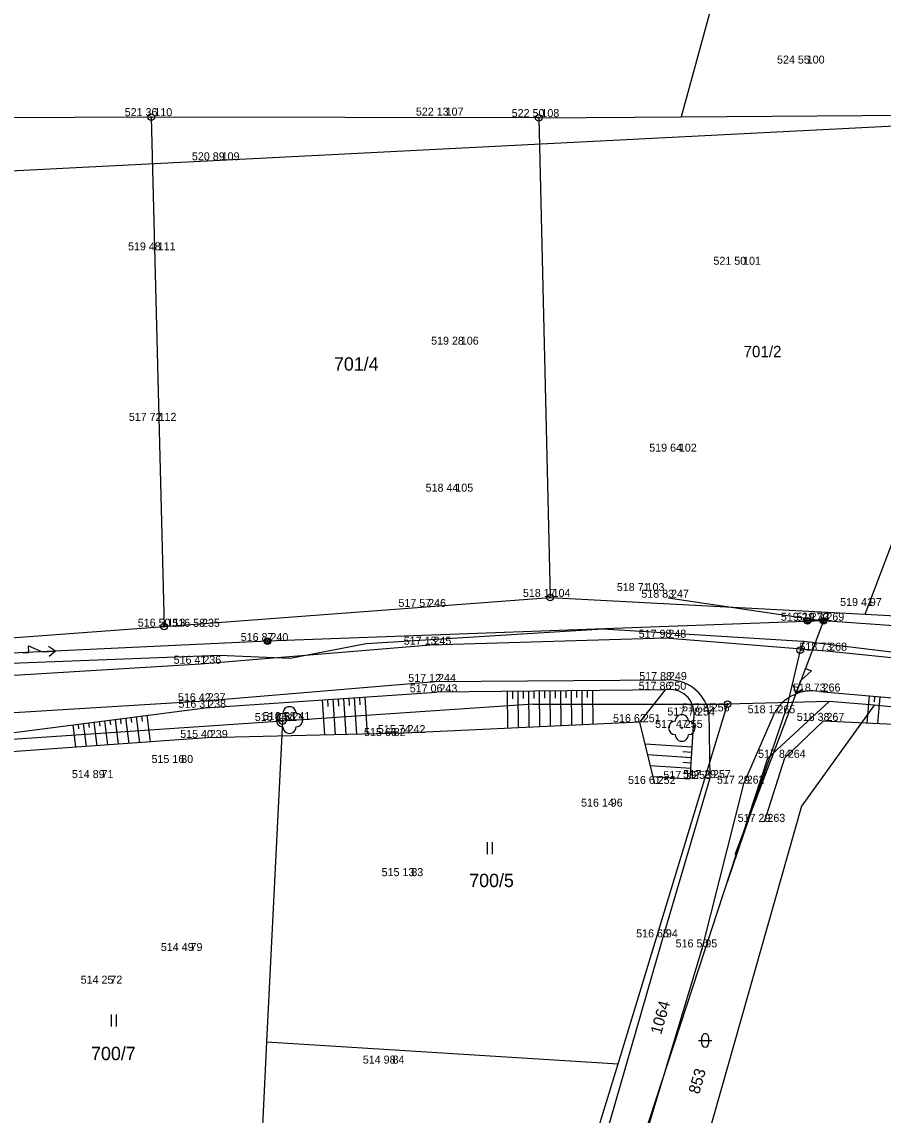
# Model space of a CAD drawing. Extents: x -553108 to -552267, y -1076883 to -1076631.
# Drawn here: x -552892.1 to -552827.6, y -1076828.5 to -1076746.6 of the extents above; entities that cross this region are included whole.
import ezdxf

# ---------------------------------------------------------------- set-up
doc = ezdxf.new("R2010")
doc.units = 0
for name, color, linetype in [('Vrstva 1', 7, 'Continuous'), ('Vrstva 12', 7, 'Continuous'), ('Vrstva 16', 7, 'Continuous'), ('Vrstva 17', 7, 'Continuous'), ('Vrstva 2', 7, 'Continuous'), ('Vrstva 20', 7, 'Continuous'), ('Vrstva 21', 7, 'Continuous'), ('Vrstva 26', 7, 'Continuous'), ('Vrstva 27', 7, 'Continuous'), ('Vrstva 3', 7, 'Continuous'), ('Vrstva 33', 7, 'Continuous'), ('Vrstva 4', 7, 'Continuous'), ('Vrstva 46', 7, 'Continuous'), ('Vrstva 5', 7, 'Continuous'), ('Vrstva 53', 7, 'Continuous'), ('Vrstva 6', 7, 'Continuous')]:
    doc.layers.add(name, color=color, linetype=linetype)

msp = doc.modelspace()

# ---------------------------------------------------------------- linework, layer by layer
at = {"layer": 'Vrstva 1'}
for centre in [(-552872.06, -1076798.89), (-552842.65, -1076799.48)]:
    msp.add_circle(centre, 0.05, dxfattribs=at)
for centre, start, end in [((-552872.559, -1076798.89), 90.11832, 269.88168), ((-552872.06, -1076798.386), 359.57041, 180.42959), ((-552871.563, -1076798.89), 270.29937, 89.70063), ((-552843.149, -1076799.48), 90.11832, 269.88168), ((-552842.65, -1076798.976), 359.57041, 180.42959), ((-552842.153, -1076799.48), 270.29937, 89.70063), ((-552872.06, -1076799.391), 179.84171, 0.15829), ((-552842.65, -1076799.981), 179.84171, 0.15829)]:
    msp.add_arc(centre, 0.5, start, end, dxfattribs=at)
at = {"layer": 'Vrstva 12'}
for p, q in [((-552834.93, -1076801.72), (-552832.03, -1076798.95)), ((-552832.03, -1076798.95), (-552822.54, -1076799.41)), ((-552836.46, -1076806.52), (-552834.93, -1076801.72))]:
    msp.add_line(p, q, dxfattribs=at)
at = {"layer": 'Vrstva 16'}
for p, q in [((-552891.597, -1076793.813), (-552891.62, -1076793.313)), ((-552891.62, -1076793.313), (-552890.598, -1076793.766)), ((-552889.599, -1076793.719), (-552890.116, -1076793.368)), ((-552892.096, -1076793.836), (-552891.597, -1076793.813)), ((-552890.598, -1076793.766), (-552889.599, -1076793.719)), ((-552889.599, -1076793.719), (-552890.081, -1076794.117)), ((-552833.214, -1076794.548), (-552833.391, -1076795.015)), ((-552833.391, -1076795.015), (-552832.923, -1076795.192)), ((-552832.923, -1076795.192), (-552833.745, -1076795.95)), ((-552834.1, -1076796.885), (-552834.273, -1076796.285)), ((-552833.745, -1076795.95), (-552834.1, -1076796.885)), ((-552834.1, -1076796.885), (-552833.572, -1076796.551))]:
    msp.add_line(p, q, dxfattribs=at)
at = {"layer": 'Vrstva 17'}
for p, q in [((-552878.74, -1076794.67), (-552861.49, -1076793.24)), ((-552861.49, -1076793.24), (-552843.88, -1076792.72)), ((-552843.88, -1076792.72), (-552831.83, -1076793.69)), ((-552831.83, -1076793.69), (-552822.33, -1076794.68)), ((-552894.1, -1076795.62), (-552878.74, -1076794.67)), ((-552843.84, -1076795.89), (-552861.15, -1076796.03)), ((-552861.15, -1076796.03), (-552878.42, -1076797.48)), ((-552832.32, -1076796.75), (-552822.3, -1076797.63)), ((-552878.42, -1076797.48), (-552893.95, -1076798.43)), ((-552840.63, -1076798.24), (-552840.54, -1076803.24)), ((-552838.01, -1076803.66), (-552835.71, -1076798.38)), ((-552840.54, -1076803.24), (-552844.07, -1076815.18)), ((-552841.11, -1076815.93), (-552838.01, -1076803.66)), ((-552844.07, -1076815.18), (-552848.68, -1076831.13)), ((-552845.93, -1076831.93), (-552841.11, -1076815.93))]:
    msp.add_line(p, q, dxfattribs=at)
for centre, radius, start, end in [((-552843.623, -1076798.961), 3.079, 13.54648, 94.03876), ((-552832.896, -1076799.892), 3.194, 79.6051, 151.75381)]:
    msp.add_arc(centre, radius, start, end, dxfattribs=at)
at = {"layer": 'Vrstva 2'}
for p, q in [((-552848.57, -1076792.08), (-552866.31, -1076793.17)), ((-552833.59, -1076793), (-552848.57, -1076792.08)), ((-552866.31, -1076793.17), (-552872.01, -1076794.27)), ((-552833.509, -1076793.01), (-552833.778, -1076793.66)), ((-552833.509, -1076793.01), (-552833.59, -1076793)), ((-552822.72, -1076794.32), (-552833.509, -1076793.01)), ((-552877.32, -1076794.06), (-552893.58, -1076794.68)), ((-552872.01, -1076794.27), (-552877.32, -1076794.06)), ((-552833.778, -1076793.66), (-552834.782, -1076797.897)), ((-552834.782, -1076797.897), (-552839.24, -1076811.03))]:
    msp.add_line(p, q, dxfattribs=at)
for centre, radius in [((-552833.22, -1076791.45), 0.25), ((-552833.22, -1076791.45), 0.16), ((-552833.22, -1076791.45), 0.05), ((-552833.77, -1076793.657), 0.25)]:
    msp.add_circle(centre, radius, dxfattribs=at)
at = {"layer": 'Vrstva 20'}
for centre, radius in [((-552832.04, -1076791.45), 0.25), ((-552832.04, -1076791.45), 0.158), ((-552832.04, -1076791.45), 0.05), ((-552873.71, -1076792.97), 0.25), ((-552873.71, -1076792.97), 0.158), ((-552873.71, -1076792.97), 0.05)]:
    msp.add_circle(centre, radius, dxfattribs=at)
at = {"layer": 'Vrstva 21'}
for p, q in [((-552949.08, -1076760.6), (-552812.457, -1076753.608)), ((-552832.04, -1076791.45), (-552873.71, -1076792.97)), ((-552832.04, -1076791.45), (-552838.685, -1076808.987)), ((-552790.19, -1076794.44), (-552832.04, -1076791.45)), ((-552873.71, -1076792.97), (-552916.58, -1076794.99))]:
    msp.add_line(p, q, dxfattribs=at)
at = {"layer": 'Vrstva 26'}
for p, q in [((-552855.697, -1076799.51), (-552855.728, -1076796.751)), ((-552855.322, -1076797.296), (-552855.328, -1076796.747)), ((-552854.897, -1076799.473), (-552854.928, -1076796.742)), ((-552854.522, -1076797.281), (-552854.528, -1076796.738)), ((-552854.098, -1076799.436), (-552854.128, -1076796.733)), ((-552853.722, -1076797.267), (-552853.728, -1076796.729)), ((-552853.298, -1076799.399), (-552853.328, -1076796.725)), ((-552852.922, -1076797.252), (-552852.928, -1076796.72)), ((-552852.499, -1076799.362), (-552852.528, -1076796.716)), ((-552852.122, -1076797.238), (-552852.128, -1076796.711)), ((-552851.699, -1076799.325), (-552851.728, -1076796.707)), ((-552851.322, -1076797.223), (-552851.328, -1076796.702)), ((-552850.899, -1076799.287), (-552850.928, -1076796.698)), ((-552850.522, -1076797.209), (-552850.528, -1076796.694)), ((-552850.1, -1076799.25), (-552850.128, -1076796.689)), ((-552849.722, -1076797.194), (-552849.728, -1076796.685)), ((-552849.3, -1076799.213), (-552849.328, -1076796.68)), ((-552869.407, -1076800.015), (-552869.583, -1076797.382)), ((-552869.149, -1076797.885), (-552869.184, -1076797.355)), ((-552868.606, -1076799.996), (-552868.785, -1076797.328)), ((-552868.35, -1076797.838), (-552868.386, -1076797.301)), ((-552867.806, -1076799.976), (-552867.987, -1076797.275)), ((-552867.551, -1076797.792), (-552867.588, -1076797.248)), ((-552867.005, -1076799.957), (-552867.188, -1076797.221)), ((-552866.753, -1076797.745), (-552866.789, -1076797.195)), ((-552866.205, -1076799.937), (-552866.39, -1076797.168)), ((-552828.755, -1076799.109), (-552828.576, -1076797.079)), ((-552828.213, -1076797.517), (-552828.178, -1076797.114)), ((-552827.955, -1076799.148), (-552827.779, -1076797.149)), ((-552887.845, -1076799.536), (-552887.889, -1076799.195)), ((-552887.27, -1076800.87), (-552887.492, -1076799.144)), ((-552887.05, -1076799.443), (-552887.095, -1076799.093)), ((-552886.47, -1076800.814), (-552886.699, -1076799.042)), ((-552886.256, -1076799.35), (-552886.302, -1076798.991)), ((-552885.671, -1076800.757), (-552885.905, -1076798.94)), ((-552885.461, -1076799.256), (-552885.509, -1076798.888)), ((-552884.872, -1076800.7), (-552885.112, -1076798.837)), ((-552884.666, -1076799.163), (-552884.715, -1076798.786)), ((-552884.072, -1076800.643), (-552884.318, -1076798.735)), ((-552883.872, -1076799.07), (-552883.922, -1076798.684)), ((-552883.273, -1076800.587), (-552883.525, -1076798.633)), ((-552883.077, -1076798.977), (-552883.128, -1076798.582)), ((-552882.474, -1076800.53), (-552882.731, -1076798.531)), ((-552888.069, -1076800.927), (-552888.286, -1076799.246)), ((-552845.408, -1076800.669), (-552841.878, -1076800.892)), ((-552845.212, -1076801.483), (-552841.928, -1076801.69)), ((-552842.584, -1076801.248), (-552841.903, -1076801.291)), ((-552845.015, -1076802.297), (-552841.979, -1076802.489)), ((-552842.585, -1076802.05), (-552841.954, -1076802.089)), ((-552844.818, -1076803.111), (-552842.029, -1076803.287)), ((-552842.586, -1076802.851), (-552842.004, -1076802.888))]:
    msp.add_line(p, q, dxfattribs=at)
at = {"layer": 'Vrstva 27'}
for p, q in [((-552843.68, -1076789.72), (-552832.04, -1076791.45)), ((-552843.88, -1076796.62), (-552861.04, -1076796.81)), ((-552845.8, -1076799.05), (-552843.88, -1076796.62)), ((-552878.38, -1076797.97), (-552861.04, -1076796.81)), ((-552893.67, -1076799.94), (-552878.38, -1076797.97)), ((-552845.8, -1076799.05), (-552863.43, -1076799.87)), ((-552844.68, -1076803.68), (-552845.8, -1076799.05)), ((-552842.03, -1076803.3), (-552841.73, -1076798.55)), ((-552863.43, -1076799.87), (-552878.25, -1076800.23)), ((-552878.25, -1076800.23), (-552899.79, -1076801.76))]:
    msp.add_line(p, q, dxfattribs=at)
msp.add_arc((-552843.561, -1076798.427), 1.835, 356.17224, 100.00074, dxfattribs=at)
at = {"layer": 'Vrstva 3'}
for p, q in [((-552833.51, -1076749.68), (-552833.51, -1076749.68)), ((-552882.41, -1076753.62), (-552882.41, -1076753.62)), ((-552860.58, -1076753.58), (-552860.58, -1076753.58)), ((-552853.4, -1076753.69), (-552853.4, -1076753.69)), ((-552877.37, -1076756.93), (-552877.37, -1076756.93)), ((-552882.16, -1076763.68), (-552882.16, -1076763.68)), ((-552838.28, -1076764.76), (-552838.28, -1076764.76)), ((-552859.44, -1076770.75), (-552859.44, -1076770.75)), ((-552882.1, -1076776.46), (-552882.1, -1076776.46)), ((-552843.09, -1076778.77), (-552843.09, -1076778.77)), ((-552859.85, -1076781.77), (-552859.85, -1076781.77)), ((-552845.52, -1076789.22), (-552845.52, -1076789.22)), ((-552852.56, -1076789.66), (-552852.56, -1076789.66)), ((-552843.68, -1076789.72), (-552843.68, -1076789.72)), ((-552861.89, -1076790.41), (-552861.89, -1076790.41)), ((-552828.78, -1076790.34), (-552828.78, -1076790.34)), ((-552833.22, -1076791.45), (-552833.22, -1076791.45)), ((-552832.04, -1076791.45), (-552832.04, -1076791.45)), ((-552881.43, -1076791.89), (-552881.43, -1076791.89)), ((-552878.84, -1076791.9), (-552878.84, -1076791.9)), ((-552873.71, -1076792.97), (-552873.71, -1076792.97)), ((-552861.49, -1076793.24), (-552861.49, -1076793.24)), ((-552843.88, -1076792.72), (-552843.88, -1076792.72)), ((-552831.83, -1076793.69), (-552831.83, -1076793.69)), ((-552878.74, -1076794.67), (-552878.74, -1076794.67)), ((-552843.84, -1076795.89), (-552843.84, -1076795.89)), ((-552861.15, -1076796.03), (-552861.15, -1076796.03)), ((-552843.88, -1076796.62), (-552843.88, -1076796.62)), ((-552832.32, -1076796.75), (-552832.32, -1076796.75)), ((-552878.42, -1076797.48), (-552878.42, -1076797.48)), ((-552861.04, -1076796.81), (-552861.04, -1076796.81)), ((-552878.38, -1076797.97), (-552878.38, -1076797.97)), ((-552840.63, -1076798.24), (-552840.63, -1076798.24)), ((-552835.71, -1076798.38), (-552835.71, -1076798.38)), ((-552872.66, -1076798.96), (-552872.66, -1076798.96)), ((-552872.06, -1076798.89), (-552872.06, -1076798.89)), ((-552845.8, -1076799.05), (-552845.8, -1076799.05)), ((-552841.73, -1076798.55), (-552841.73, -1076798.55)), ((-552832.03, -1076798.95), (-552832.03, -1076798.95)), ((-552863.43, -1076799.87), (-552863.43, -1076799.87)), ((-552842.65, -1076799.48), (-552842.65, -1076799.48)), ((-552878.25, -1076800.23), (-552878.25, -1076800.23)), ((-552864.47, -1076800.09), (-552864.47, -1076800.09)), ((-552880.4, -1076802.11), (-552880.4, -1076802.11)), ((-552834.93, -1076801.72), (-552834.93, -1076801.72)), ((-552886.37, -1076803.24), (-552886.37, -1076803.24)), ((-552842.03, -1076803.3), (-552842.03, -1076803.3)), ((-552840.54, -1076803.24), (-552840.54, -1076803.24)), ((-552844.68, -1076803.68), (-552844.68, -1076803.68)), ((-552838.01, -1076803.66), (-552838.01, -1076803.66)), ((-552848.2, -1076805.38), (-552848.2, -1076805.38)), ((-552836.46, -1076806.52), (-552836.46, -1076806.52)), ((-552863.15, -1076810.59), (-552863.15, -1076810.59)), ((-552844.07, -1076815.18), (-552844.07, -1076815.18)), ((-552879.7, -1076816.2), (-552879.7, -1076816.2)), ((-552841.11, -1076815.93), (-552841.11, -1076815.93)), ((-552885.71, -1076818.65), (-552885.71, -1076818.65)), ((-552864.56, -1076824.64), (-552864.56, -1076824.64))]:
    msp.add_line(p, q, dxfattribs=at)
at = {"layer": 'Vrstva 33'}
for centre, radius in [((-552882.42, -1076753.7), 0.25), ((-552882.42, -1076753.7), 0.05), ((-552853.38, -1076753.74), 0.25), ((-552853.38, -1076753.74), 0.05), ((-552852.53, -1076789.7), 0.25), ((-552852.53, -1076789.7), 0.05), ((-552881.45, -1076791.87), 0.25), ((-552881.45, -1076791.87), 0.05), ((-552872.59, -1076798.97), 0.25), ((-552872.59, -1076798.97), 0.05)]:
    msp.add_circle(centre, radius, dxfattribs=at)
at = {"layer": 'Vrstva 46'}
for p, q in [((-552839.59, -1076742.27), (-552842.7, -1076753.67)), ((-552882.42, -1076753.7), (-552911.43, -1076753.82)), ((-552853.38, -1076753.74), (-552882.42, -1076753.7)), ((-552882.42, -1076753.7), (-552881.45, -1076791.87)), ((-552853.38, -1076753.74), (-552842.7, -1076753.67)), ((-552853.38, -1076753.74), (-552852.53, -1076789.7)), ((-552842.7, -1076753.67), (-552807.25, -1076753.41)), ((-552828.91, -1076790.96), (-552820.24, -1076768.06)), ((-552881.45, -1076791.87), (-552852.53, -1076789.7)), ((-552852.53, -1076789.7), (-552828.91, -1076790.96)), ((-552828.91, -1076790.96), (-552824.4, -1076791.18)), ((-552910.41, -1076794.05), (-552881.45, -1076791.87)), ((-552831.61, -1076797.51), (-552839.22, -1076797.7)), ((-552836.21, -1076801.75), (-552831.61, -1076797.51)), ((-552828.24, -1076797.77), (-552831.61, -1076797.51)), ((-552853.76, -1076797.7), (-552872.59, -1076798.97)), ((-552853.76, -1076797.7), (-552839.22, -1076797.7)), ((-552847.43, -1076824.65), (-552839.22, -1076797.7)), ((-552828.24, -1076797.77), (-552833.69, -1076805.34)), ((-552792.08, -1076801.29), (-552828.24, -1076797.77)), ((-552872.59, -1076798.97), (-552896.7, -1076800.6)), ((-552872.59, -1076798.97), (-552873.78, -1076823.01)), ((-552851.16, -1076847.43), (-552836.21, -1076801.75)), ((-552833.69, -1076805.34), (-552846.57, -1076850.74)), ((-552873.78, -1076823.01), (-552875.41, -1076856.04)), ((-552873.78, -1076823.01), (-552847.43, -1076824.65)), ((-552854.11, -1076846.55), (-552847.43, -1076824.65))]:
    msp.add_line(p, q, dxfattribs=at)
at = {"layer": 'Vrstva 5'}
for radius in [0.25, 0.05]:
    msp.add_circle((-552839.22, -1076797.7), radius, dxfattribs=at)
at = {"layer": 'Vrstva 53'}
for p, q in [((-552857.232, -1076808.031), (-552857.232, -1076808.931)), ((-552856.857, -1076808.031), (-552856.857, -1076808.931)), ((-552885.428, -1076820.954), (-552885.428, -1076821.854)), ((-552885.053, -1076820.954), (-552885.053, -1076821.854)), ((-552841.394, -1076822.906), (-552840.394, -1076822.906)), ((-552841.144, -1076823.156), (-552841.144, -1076822.656)), ((-552840.644, -1076822.656), (-552840.644, -1076823.156))]:
    msp.add_line(p, q, dxfattribs=at)
for centre, start, end in [((-552840.894, -1076822.655), 359.70034, 180.29966), ((-552840.894, -1076823.155), 180.24074, 359.75926)]:
    msp.add_arc(centre, 0.25, start, end, dxfattribs=at)

# ---------------------------------------------------------------- texts
at = {"layer": 'Vrstva 4'}
for s, p in [(' 100', (-552833.51, -1076749.68)), (' 110', (-552882.41, -1076753.62)), (' 107', (-552860.58, -1076753.58)), (' 108', (-552853.4, -1076753.69)), (' 109', (-552877.37, -1076756.93)), (' 111', (-552882.16, -1076763.68)), (' 101', (-552838.28, -1076764.76)), (' 106', (-552859.44, -1076770.75)), (' 112', (-552882.1, -1076776.46)), (' 102', (-552843.09, -1076778.77)), (' 105', (-552859.85, -1076781.77)), (' 104', (-552852.56, -1076789.66)), (' 103', (-552845.52, -1076789.22)), (' 247', (-552843.68, -1076789.72)), (' 246', (-552861.89, -1076790.41)), (' 97', (-552828.78, -1076790.34)), (' 270', (-552833.22, -1076791.45)), (' 269', (-552832.04, -1076791.45)), (' 113', (-552881.43, -1076791.89)), (' 235', (-552878.84, -1076791.9)), (' 240', (-552873.71, -1076792.97)), (' 245', (-552861.49, -1076793.24)), (' 248', (-552843.88, -1076792.72)), (' 268', (-552831.83, -1076793.69)), (' 236', (-552878.74, -1076794.67)), (' 244', (-552861.15, -1076796.03)), (' 249', (-552843.84, -1076795.89)), (' 243', (-552861.04, -1076796.81)), (' 250', (-552843.88, -1076796.62)), (' 266', (-552832.32, -1076796.75)), (' 237', (-552878.42, -1076797.48)), (' 238', (-552878.38, -1076797.97)), (' 81', (-552872.66, -1076798.96)), (' 241', (-552872.06, -1076798.89)), (' 254', (-552841.73, -1076798.55)), (' 256', (-552840.63, -1076798.24)), (' 265', (-552835.71, -1076798.38)), (' 267', (-552832.03, -1076798.95)), (' 251', (-552845.8, -1076799.05)), (' 255', (-552842.65, -1076799.48)), (' 239', (-552878.25, -1076800.23)), (' 82', (-552864.47, -1076800.09)), (' 242', (-552863.43, -1076799.87)), (' 80', (-552880.4, -1076802.11)), (' 264', (-552834.93, -1076801.72)), (' 71', (-552886.37, -1076803.24)), (' 252', (-552844.68, -1076803.68)), (' 253', (-552842.03, -1076803.3)), (' 257', (-552840.54, -1076803.24)), (' 262', (-552838.01, -1076803.66)), (' 96', (-552848.2, -1076805.38)), (' 263', (-552836.46, -1076806.52)), (' 83', (-552863.15, -1076810.59)), (' 94', (-552844.07, -1076815.18)), (' 79', (-552879.7, -1076816.2)), (' 95', (-552841.11, -1076815.93)), (' 72', (-552885.71, -1076818.65)), (' 84', (-552864.56, -1076824.64))]:
    msp.add_text(s, height=0.6, dxfattribs=at).set_placement(p)
at = {"layer": 'Vrstva 53'}
for s, height, p in [('701/2', 0.85, (-552838.023, -1076771.69)), ('701/4', 1, (-552868.728, -1076772.698)), ('700/5', 1, (-552858.587, -1076811.41)), ('700/7', 1, (-552886.935, -1076824.382))]:
    msp.add_text(s, height=height, dxfattribs=at).set_placement(p)
for s, p in [('1064', (-552844.206, -1076822.511)), ('853', (-552841.355, -1076826.979))]:
    msp.add_text(s, height=0.85, rotation=74.16135, dxfattribs=at).set_placement(p)
at = {"layer": 'Vrstva 6'}
for s, p in [('524 55', (-552835.514, -1076749.68)), ('521 36', (-552884.414, -1076753.62)), ('522 13', (-552862.584, -1076753.58)), ('522 50', (-552855.404, -1076753.69)), ('520 89', (-552879.374, -1076756.93)), ('519 48', (-552884.164, -1076763.68)), ('521 50', (-552840.284, -1076764.76)), ('519 28', (-552861.444, -1076770.75)), ('517 72', (-552884.104, -1076776.46)), ('519 64', (-552845.094, -1076778.77)), ('518 44', (-552861.854, -1076781.77)), ('518 17', (-552854.564, -1076789.66)), ('518 71', (-552847.524, -1076789.22)), ('518 83', (-552845.684, -1076789.72)), ('517 57', (-552863.894, -1076790.41)), ('519 41', (-552830.784, -1076790.34)), ('519 21', (-552835.224, -1076791.45)), ('519 33', (-552834.044, -1076791.45)), ('516 50', (-552883.434, -1076791.89)), ('516 58', (-552880.844, -1076791.9)), ('516 87', (-552875.714, -1076792.97)), ('517 13', (-552863.494, -1076793.24)), ('517 98', (-552845.884, -1076792.72)), ('518 73', (-552833.834, -1076793.69)), ('516 41', (-552880.744, -1076794.67)), ('517 12', (-552863.154, -1076796.03)), ('517 88', (-552845.844, -1076795.89)), ('517 06', (-552863.044, -1076796.81)), ('517 86', (-552845.884, -1076796.62)), ('518 73', (-552834.324, -1076796.75)), ('516 42', (-552880.424, -1076797.48)), ('516 31', (-552880.384, -1076797.97)), ('516 25', (-552874.664, -1076798.96)), ('516 58', (-552874.064, -1076798.89)), ('517 78', (-552843.734, -1076798.55)), ('517 85', (-552842.634, -1076798.24)), ('518 17', (-552837.714, -1076798.38)), ('518 38', (-552834.034, -1076798.95)), ('516 62', (-552847.804, -1076799.05)), ('517 47', (-552844.654, -1076799.48)), ('515 40', (-552880.254, -1076800.23)), ('515 66', (-552866.474, -1076800.09)), ('515 74', (-552865.434, -1076799.87)), ('515 16', (-552882.404, -1076802.11)), ('517 84', (-552836.934, -1076801.72)), ('514 89', (-552888.374, -1076803.24)), ('516 61', (-552846.684, -1076803.68)), ('517 19', (-552844.034, -1076803.3)), ('517 29', (-552842.544, -1076803.24)), ('517 29', (-552840.014, -1076803.66)), ('516 14', (-552850.204, -1076805.38)), ('517 29', (-552838.464, -1076806.52)), ('515 13', (-552865.154, -1076810.59)), ('516 65', (-552846.074, -1076815.18)), ('514 49', (-552881.704, -1076816.2)), ('516 56', (-552843.114, -1076815.93)), ('514 25', (-552887.714, -1076818.65)), ('514 98', (-552866.564, -1076824.64))]:
    msp.add_text(s, height=0.6, dxfattribs=at).set_placement(p)

doc.saveas('drawing.dxf')
